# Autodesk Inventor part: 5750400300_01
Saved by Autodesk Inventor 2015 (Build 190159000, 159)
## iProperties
Created: 2020-07
Part Number: 5750400300_01
Checked By: TraceParts S.A.
Material: Generic
Catalog Web Link: www.traceparts.com
Document SubType Name: Modeling
Designer: TraceParts
Density: 1 g/cm^3
Appearance: Default
Company: TraceParts S.A.
Author: TraceParts
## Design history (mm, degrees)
feature "5750400300_01.ipt"
body "Solid1"
